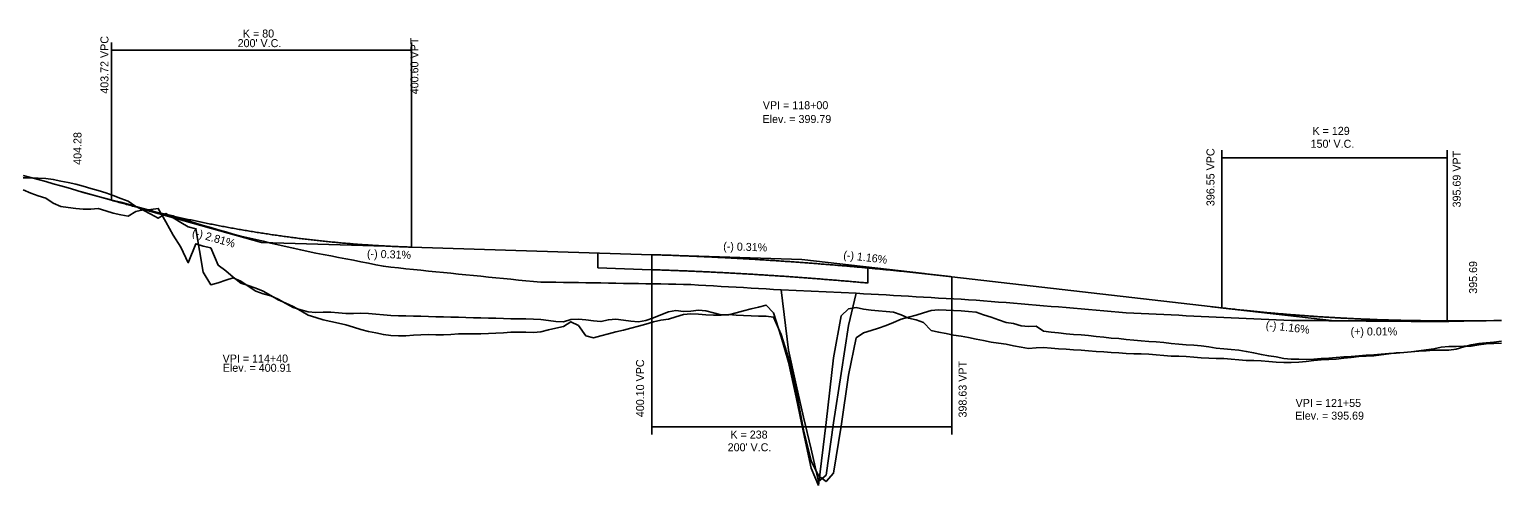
# Model space of a CAD drawing. Extents: x 2084170 to 2089570, y 1072039 to 1077242.
# Drawn here: x 2086175 to 2087155, y 1075386 to 1075690 of the extents above; entities that cross this region are included whole.
import ezdxf

# ---------------------------------------------------------------- set-up
doc = ezdxf.new("R2010")
doc.units = 0
for name, color, linetype in [('RD_DDB_GradeTX', 7, 'Continuous'), ('RD_DDB_Profile_EX', 7, 'Continuous'), ('RD_DDB_Profile_Lbl', 7, 'Continuous'), ('RD_DDB_Profile_PR', 7, 'Continuous'), ('RD_DDB_StripGrade', 7, 'Continuous'), ('RD_DDB_VCLbl', 7, 'Continuous'), ('RD_PD_Bridge', 7, 'Continuous'), ('RD_Sketch1', 7, 'Continuous'), ('RD_Sketch3', 7, 'Continuous'), ('RD_Sketch4', 7, 'Continuous')]:
    doc.layers.add(name, color=color, linetype=linetype)

msp = doc.modelspace()

# ---------------------------------------------------------------- linework, layer by layer
at = {"layer": 'RD_DDB_GradeTX'}
for p, q in [((2086250.56, 1075570.58), (2086329.89, 1075548.31)), ((2086412.25, 1075545.73), (2086329.89, 1075548.31)), ((2086607.53, 1075539.61), (2086689.89, 1075537.03)), ((2086771.75, 1075527.58), (2086689.89, 1075537.03)), ((2086963.04, 1075505.48), (2087044.89, 1075496.03)), ((2087127.29, 1075496.09), (2087044.89, 1075496.03))]:
    msp.add_line(p, q, dxfattribs=at)
at = {"layer": 'RD_DDB_Profile_EX'}
for points in [[(2086171.05, 1075592.84), (2086176.05, 1075591.58), (2086181.05, 1075590.21), (2086186.05, 1075588.83), (2086191.05, 1075587.45), (2086196.05, 1075586.03), (2086201.05, 1075584.6)], [(2086201.05, 1075584.6), (2086206.05, 1075583.14), (2086211.05, 1075581.66), (2086216.05, 1075580.21), (2086221.05, 1075578.94), (2086226.05, 1075577.65), (2086231.05, 1075576.35), (2086236.05, 1075575.03), (2086241.05, 1075573.69), (2086246.05, 1075572.33), (2086251.05, 1075570.96), (2086256.05, 1075569.57), (2086261.05, 1075568.13), (2086266.05, 1075566.73), (2086271.05, 1075565.37), (2086276.05, 1075563.99), (2086281.05, 1075562.6), (2086286.05, 1075561.16), (2086291.05, 1075559.67), (2086296.05, 1075558.24), (2086301.05, 1075556.8), (2086306.05, 1075555.35), (2086311.05, 1075553.85), (2086316.05, 1075552.46), (2086321.05, 1075551.32), (2086326.05, 1075550.2), (2086331.05, 1075549.06), (2086336.05, 1075547.93), (2086341.05, 1075546.79), (2086346.05, 1075545.65), (2086351.05, 1075544.52), (2086356.05, 1075543.38), (2086361.05, 1075542.25), (2086366.05, 1075541.19), (2086371.05, 1075540.24), (2086376.05, 1075539.29), (2086381.05, 1075538.34), (2086386.05, 1075537.38), (2086391.05, 1075536.43), (2086396.05, 1075535.44), (2086401.05, 1075534.46), (2086406.05, 1075533.48), (2086411.05, 1075532.5), (2086416.05, 1075531.8), (2086421.05, 1075531.29), (2086426.05, 1075530.79), (2086431.05, 1075530.28), (2086436.05, 1075529.77), (2086441.05, 1075529.28), (2086446.05, 1075528.77), (2086451.05, 1075528.27), (2086456.05, 1075527.76), (2086461.05, 1075527.25), (2086466.05, 1075526.77), (2086471.05, 1075526.26), (2086476.05, 1075525.75), (2086481.05, 1075525.25), (2086486.05, 1075524.74), (2086491.05, 1075524.26), (2086496.05, 1075523.75), (2086501.05, 1075523.25), (2086506.05, 1075522.75), (2086511.05, 1075522.24), (2086516.05, 1075521.94), (2086521.05, 1075521.85), (2086526.05, 1075521.77), (2086531.05, 1075521.68), (2086536.05, 1075521.6), (2086541.05, 1075521.54), (2086546.05, 1075521.46), (2086551.05, 1075521.37), (2086556.05, 1075521.29), (2086561.05, 1075521.2), (2086566.05, 1075521.14), (2086571.05, 1075521.06), (2086576.05, 1075520.97), (2086581.05, 1075520.89), (2086586.05, 1075520.8), (2086591.05, 1075520.74), (2086596.05, 1075520.65), (2086601.05, 1075520.56), (2086606.05, 1075520.48), (2086611.05, 1075520.39), (2086616.05, 1075520.2), (2086621.05, 1075519.91), (2086626.05, 1075519.61), (2086631.05, 1075519.32), (2086636.05, 1075519.02), (2086641.05, 1075518.79), (2086646.05, 1075518.5), (2086651.05, 1075518.2), (2086656.05, 1075517.91), (2086661.05, 1075517.61), (2086666.05, 1075517.35), (2086671.05, 1075517.06), (2086676.05, 1075516.76), (2086681.05, 1075476.62), (2086686.05, 1075453.49), (2086691.05, 1075431.99), (2086696.05, 1075410.5), (2086701.05, 1075389.01)], [(2086701.05, 1075389.01), (2086706.05, 1075393.3), (2086711.05, 1075428.06), (2086716.05, 1075461.05), (2086721.05, 1075493), (2086726.05, 1075514.45), (2086731.05, 1075514.17), (2086736.05, 1075513.89), (2086741.05, 1075513.6), (2086746.05, 1075513.32), (2086751.05, 1075512.99), (2086756.05, 1075512.71), (2086761.05, 1075512.43), (2086766.05, 1075512.15), (2086771.05, 1075511.87), (2086776.05, 1075511.55), (2086781.05, 1075511.27), (2086786.05, 1075510.99), (2086791.05, 1075510.71), (2086796.05, 1075510.43), (2086801.05, 1075510.12), (2086806.05, 1075509.84), (2086811.05, 1075509.45), (2086816.05, 1075509.03), (2086821.05, 1075508.62), (2086826.05, 1075508.21), (2086831.05, 1075507.8), (2086836.05, 1075507.39), (2086841.05, 1075506.98), (2086846.05, 1075506.57), (2086851.05, 1075506.15), (2086856.05, 1075505.74), (2086861.05, 1075505.31), (2086866.05, 1075504.89), (2086871.05, 1075504.46), (2086876.05, 1075504.04), (2086881.05, 1075503.61), (2086886.05, 1075503.19), (2086891.05, 1075502.76), (2086896.05, 1075502.34), (2086901.05, 1075501.91), (2086906.05, 1075501.49), (2086911.05, 1075501.15), (2086916.05, 1075500.92), (2086921.05, 1075500.69), (2086926.05, 1075500.46), (2086931.05, 1075500.23), (2086936.05, 1075499.99), (2086941.05, 1075499.76), (2086946.05, 1075499.53), (2086951.05, 1075499.3), (2086956.05, 1075499.07), (2086961.05, 1075498.83), (2086966.05, 1075498.6), (2086971.05, 1075498.37), (2086976.05, 1075498.14), (2086981.05, 1075497.91), (2086986.05, 1075497.68), (2086991.05, 1075497.45), (2086996.05, 1075497.22), (2087001.05, 1075496.99), (2087006.05, 1075496.75), (2087011.05, 1075496.52), (2087016.05, 1075496.38), (2087021.05, 1075496.34), (2087026.05, 1075496.31), (2087031.05, 1075496.27), (2087036.05, 1075496.22), (2087041.05, 1075496.18), (2087046.05, 1075496.14), (2087051.05, 1075496.1), (2087056.05, 1075496.05), (2087061.05, 1075496.01), (2087066.05, 1075495.97), (2087071.05, 1075495.93), (2087076.05, 1075495.89), (2087081.05, 1075495.84), (2087086.05, 1075495.8), (2087091.05, 1075495.77), (2087096.05, 1075495.72), (2087101.05, 1075495.68), (2087106.05, 1075495.64), (2087111.05, 1075495.6), (2087116.05, 1075495.67), (2087121.05, 1075495.75), (2087126.05, 1075495.83), (2087131.05, 1075495.91), (2087136.05, 1075496), (2087141.05, 1075496.08), (2087146.05, 1075496.16), (2087151.05, 1075496.24), (2087156.05, 1075496.32)]]:
    msp.add_lwpolyline(points, dxfattribs=at)
at = {"layer": 'RD_DDB_Profile_PR'}
for p, q in [((2086209.89, 1075582), (2086229.89, 1075576.39)), ((2086429.89, 1075545.17), (2086589.89, 1075540.16)), ((2086789.89, 1075525.48), (2086969.89, 1075504.69)), ((2087119.89, 1075496.09), (2087139.89, 1075496.1))]:
    msp.add_line(p, q, dxfattribs=at)
for points in [[(2086229.89, 1075576.39), (2086233.89, 1075575.27), (2086237.89, 1075574.18), (2086241.89, 1075573.11), (2086245.89, 1075572.05), (2086249.89, 1075571.02), (2086253.89, 1075570.01), (2086257.89, 1075569.01), (2086261.89, 1075568.04), (2086265.89, 1075567.09), (2086269.89, 1075566.15), (2086273.89, 1075565.24), (2086277.89, 1075564.35), (2086281.89, 1075563.47), (2086285.89, 1075562.62), (2086289.89, 1075561.78), (2086293.89, 1075560.97), (2086297.89, 1075560.18), (2086301.89, 1075559.4), (2086305.89, 1075558.65), (2086309.89, 1075557.91), (2086313.89, 1075557.2), (2086317.89, 1075556.51), (2086321.89, 1075555.83), (2086325.89, 1075555.18), (2086329.89, 1075554.54), (2086333.89, 1075553.93), (2086337.89, 1075553.33), (2086341.89, 1075552.76), (2086345.89, 1075552.21), (2086349.89, 1075551.67), (2086353.89, 1075551.16), (2086357.89, 1075550.66), (2086361.89, 1075550.19), (2086365.89, 1075549.73), (2086369.89, 1075549.3), (2086373.89, 1075548.88), (2086377.89, 1075548.49), (2086381.89, 1075548.11), (2086385.89, 1075547.76), (2086389.89, 1075547.42), (2086393.89, 1075547.11), (2086397.89, 1075546.82), (2086401.89, 1075546.54), (2086405.89, 1075546.29), (2086409.89, 1075546.05), (2086413.89, 1075545.83), (2086417.89, 1075545.64), (2086421.89, 1075545.46), (2086425.89, 1075545.31), (2086429.89, 1075545.17)], [(2086589.89, 1075540.16), (2086593.89, 1075540.04), (2086597.89, 1075539.9), (2086601.89, 1075539.76), (2086605.89, 1075539.61), (2086609.89, 1075539.45), (2086613.89, 1075539.29), (2086617.89, 1075539.12), (2086621.89, 1075538.95), (2086625.89, 1075538.76), (2086629.89, 1075538.57), (2086633.89, 1075538.38), (2086637.89, 1075538.18), (2086641.89, 1075537.97), (2086645.89, 1075537.75), (2086649.89, 1075537.53), (2086653.89, 1075537.3), (2086657.89, 1075537.06), (2086661.89, 1075536.82), (2086665.89, 1075536.57), (2086669.89, 1075536.31), (2086673.89, 1075536.05), (2086677.89, 1075535.78), (2086681.89, 1075535.5), (2086685.89, 1075535.22), (2086689.89, 1075534.93), (2086693.89, 1075534.63), (2086697.89, 1075534.33), (2086701.89, 1075534.02), (2086705.89, 1075533.7), (2086709.89, 1075533.38), (2086713.89, 1075533.05), (2086717.89, 1075532.71), (2086721.89, 1075532.36), (2086725.89, 1075532.01), (2086729.89, 1075531.66), (2086733.89, 1075531.29), (2086737.89, 1075530.92), (2086741.89, 1075530.54), (2086745.89, 1075530.16), (2086749.89, 1075529.77), (2086753.89, 1075529.37), (2086757.89, 1075528.96), (2086761.89, 1075528.55), (2086765.89, 1075528.13), (2086769.89, 1075527.71), (2086773.89, 1075527.28), (2086777.89, 1075526.84), (2086781.89, 1075526.39), (2086785.89, 1075525.94), (2086789.89, 1075525.48)], [(2086969.89, 1075504.69), (2086972.89, 1075504.35), (2086975.89, 1075504.01), (2086978.89, 1075503.68), (2086981.89, 1075503.36), (2086984.89, 1075503.05), (2086987.89, 1075502.74), (2086990.89, 1075502.44), (2086993.89, 1075502.14), (2086996.89, 1075501.86), (2086999.89, 1075501.58), (2087002.89, 1075501.3), (2087005.89, 1075501.04), (2087008.89, 1075500.78), (2087011.89, 1075500.52), (2087014.89, 1075500.28), (2087017.89, 1075500.04), (2087020.89, 1075499.81), (2087023.89, 1075499.59), (2087026.89, 1075499.37), (2087029.89, 1075499.16), (2087032.89, 1075498.95), (2087035.89, 1075498.76), (2087038.89, 1075498.57), (2087041.89, 1075498.38), (2087044.89, 1075498.21), (2087047.89, 1075498.04), (2087050.89, 1075497.88), (2087053.89, 1075497.72), (2087056.89, 1075497.58), (2087059.89, 1075497.44), (2087062.89, 1075497.3), (2087065.89, 1075497.18), (2087068.89, 1075497.06), (2087071.89, 1075496.94), (2087074.89, 1075496.84), (2087077.89, 1075496.74), (2087080.89, 1075496.65), (2087083.89, 1075496.56), (2087086.89, 1075496.48), (2087089.89, 1075496.41), (2087092.89, 1075496.35), (2087095.89, 1075496.29), (2087098.89, 1075496.24), (2087101.89, 1075496.2), (2087104.89, 1075496.16), (2087107.89, 1075496.13), (2087110.89, 1075496.11), (2087113.89, 1075496.1), (2087116.89, 1075496.09), (2087119.89, 1075496.09)]]:
    msp.add_spline(points, degree=3, dxfattribs=at)
at = {"layer": 'RD_DDB_VCLbl'}
for p, q in [((2086229.89, 1075681.39), (2086229.89, 1075576.39)), ((2086429.89, 1075681.39), (2086429.89, 1075545.17)), ((2086229.89, 1075676.39), (2086429.89, 1075676.39)), ((2086969.89, 1075609.69), (2086969.89, 1075504.69)), ((2086969.89, 1075604.69), (2087119.89, 1075604.69)), ((2087119.89, 1075609.69), (2087119.89, 1075496.09)), ((2086589.89, 1075420.48), (2086589.89, 1075540.16)), ((2086789.89, 1075420.48), (2086789.89, 1075525.48)), ((2086589.89, 1075425.48), (2086789.89, 1075425.48))]:
    msp.add_line(p, q, dxfattribs=at)
at = {"layer": 'RD_PD_Bridge'}
for p, q in [((2086553.89, 1075531.29), (2086553.89, 1075541.29)), ((2086553.89, 1075531.29), (2086589.58, 1075530.17)), ((2086733.89, 1075521.25), (2086733.89, 1075531.29))]:
    msp.add_line(p, q, dxfattribs=at)
msp.add_spline([(2086589.57, 1075530.17), (2086593.56, 1075530.04), (2086597.55, 1075529.91), (2086601.53, 1075529.76), (2086605.51, 1075529.62), (2086609.5, 1075529.46), (2086613.48, 1075529.3), (2086617.46, 1075529.13), (2086621.45, 1075528.96), (2086625.43, 1075528.77), (2086629.41, 1075528.59), (2086633.4, 1075528.39), (2086637.38, 1075528.19), (2086641.36, 1075527.98), (2086645.35, 1075527.77), (2086649.33, 1075527.54), (2086653.31, 1075527.31), (2086657.3, 1075527.08), (2086661.28, 1075526.84), (2086665.26, 1075526.59), (2086669.24, 1075526.33), (2086673.23, 1075526.07), (2086677.21, 1075525.8), (2086681.19, 1075525.53), (2086685.18, 1075525.24), (2086689.16, 1075524.95), (2086693.14, 1075524.66), (2086697.13, 1075524.36), (2086701.11, 1075524.05), (2086705.09, 1075523.73), (2086709.08, 1075523.41), (2086713.06, 1075523.08), (2086717.04, 1075522.74), (2086721.03, 1075522.4), (2086725.01, 1075522.05), (2086728.99, 1075521.7), (2086732.98, 1075521.33), (2086733.89, 1075521.25)], degree=3, dxfattribs=at)
at = {"layer": 'RD_Sketch1'}
msp.add_line((2086676.05, 1075516.76), (2086726.05, 1075514.45), dxfattribs=at)
at = {"layer": 'RD_Sketch3'}
for points in [[(2086171.05, 1075583.29), (2086176.05, 1075581.17), (2086181.05, 1075579.34), (2086186.05, 1075577.81), (2086191.05, 1075574.46), (2086196.05, 1075572.3), (2086201.05, 1075571.49)], [(2086201.05, 1075571.49), (2086206.05, 1075570.92), (2086211.05, 1075570.58), (2086216.05, 1075570.54), (2086221.05, 1075570.93), (2086226.05, 1075569.27), (2086231.05, 1075567.88), (2086236.05, 1075566.75), (2086241.05, 1075565.9), (2086246.05, 1075568.89), (2086251.05, 1075570.01), (2086256.05, 1075570.35), (2086261.05, 1075571.01), (2086266.05, 1075562.13), (2086271.05, 1075553.15), (2086276.05, 1075545.24), (2086281.05, 1075534.74), (2086286.05, 1075547.46), (2086291.05, 1075545.91), (2086296.05, 1075544.78), (2086301.05, 1075533.15), (2086306.05, 1075529.48), (2086311.05, 1075525.09), (2086316.05, 1075521.22), (2086321.05, 1075519.64), (2086326.05, 1075517.89), (2086331.05, 1075515.92), (2086336.05, 1075512.97), (2086341.05, 1075510.08), (2086346.05, 1075507.88), (2086351.05, 1075505.68), (2086356.05, 1075502.73), (2086361.05, 1075499.97), (2086366.05, 1075498.38), (2086371.05, 1075496.78), (2086376.05, 1075495.57), (2086381.05, 1075494.6), (2086386.05, 1075493.51), (2086391.05, 1075491.88), (2086396.05, 1075490.26), (2086401.05, 1075488.96), (2086406.05, 1075488), (2086411.05, 1075486.9), (2086416.05, 1075486.24), (2086421.05, 1075486.12), (2086426.05, 1075486.12), (2086431.05, 1075486.48), (2086436.05, 1075486.85), (2086441.05, 1075486.97), (2086446.05, 1075486.86), (2086451.05, 1075486.77), (2086456.05, 1075487.09), (2086461.05, 1075487.41), (2086466.05, 1075487.52), (2086471.05, 1075487.42), (2086476.05, 1075487.32), (2086481.05, 1075487.56), (2086486.05, 1075487.85), (2086491.05, 1075488.14), (2086496.05, 1075488.43), (2086501.05, 1075488.51), (2086506.05, 1075488.43), (2086511.05, 1075488.34), (2086516.05, 1075488.78), (2086521.05, 1075490), (2086526.05, 1075491.21), (2086531.05, 1075492.42), (2086536.05, 1075495.51), (2086541.05, 1075492.97), (2086546.05, 1075486.18), (2086551.05, 1075484.82), (2086556.05, 1075486.16), (2086561.05, 1075487.5), (2086566.05, 1075488.8), (2086571.05, 1075489.9), (2086576.05, 1075491.22), (2086581.05, 1075492.59), (2086586.05, 1075493.96), (2086591.05, 1075495.33), (2086596.05, 1075496.45), (2086601.05, 1075497.1), (2086606.05, 1075498.74), (2086611.05, 1075500.39), (2086616.05, 1075500.75), (2086621.05, 1075500.46), (2086626.05, 1075500.16), (2086631.05, 1075499.86), (2086636.05, 1075499.82), (2086641.05, 1075500.21), (2086646.05, 1075499.97), (2086651.05, 1075499.74), (2086656.05, 1075499.5), (2086661.05, 1075499.27), (2086666.05, 1075499.12), (2086671.05, 1075498.43), (2086676.05, 1075486.91), (2086681.05, 1075471.48), (2086686.05, 1075449.59), (2086691.05, 1075423.46), (2086696.05, 1075402.85), (2086701.05, 1075392.76)], [(2086701.05, 1075392.76), (2086706.05, 1075389.02), (2086711.05, 1075394.71), (2086716.05, 1075425.99), (2086721.05, 1075459.99), (2086726.05, 1075484.69), (2086731.05, 1075488.04), (2086736.05, 1075489.66), (2086741.05, 1075491.28), (2086746.05, 1075492.9), (2086751.05, 1075494.94), (2086756.05, 1075497.14), (2086761.05, 1075498.54), (2086766.05, 1075499.94), (2086771.05, 1075501.35), (2086776.05, 1075502.89), (2086781.05, 1075503.52), (2086786.05, 1075503.26), (2086791.05, 1075503), (2086796.05, 1075502.74), (2086801.05, 1075502.38), (2086806.05, 1075501.91), (2086811.05, 1075500.19), (2086816.05, 1075498.47), (2086821.05, 1075496.75), (2086826.05, 1075495.02), (2086831.05, 1075494.41), (2086836.05, 1075492.74), (2086841.05, 1075492.27), (2086846.05, 1075492.62), (2086851.05, 1075489.15), (2086856.05, 1075488.6), (2086861.05, 1075488.04), (2086866.05, 1075487.48), (2086871.05, 1075486.93), (2086876.05, 1075486.86), (2086881.05, 1075486.28), (2086886.05, 1075485.7), (2086891.05, 1075485.11), (2086896.05, 1075484.53), (2086901.05, 1075484.29), (2086906.05, 1075483.68), (2086911.05, 1075483.13), (2086916.05, 1075482.77), (2086921.05, 1075482.41), (2086926.05, 1075482.05), (2086931.05, 1075481.68), (2086936.05, 1075481.09), (2086941.05, 1075480.59), (2086946.05, 1075480.2), (2086951.05, 1075479.81), (2086956.05, 1075479.42), (2086961.05, 1075478.74), (2086966.05, 1075477.92), (2086971.05, 1075477.37), (2086976.05, 1075476.94), (2086981.05, 1075476.5), (2086986.05, 1075475.69), (2086991.05, 1075474.68), (2086996.05, 1075473.68), (2087001.05, 1075472.67), (2087006.05, 1075472.08), (2087011.05, 1075471.01), (2087016.05, 1075470.64), (2087021.05, 1075470.52), (2087026.05, 1075470.41), (2087031.05, 1075470.54), (2087036.05, 1075470.92), (2087041.05, 1075471.29), (2087046.05, 1075471.67), (2087051.05, 1075472.04), (2087056.05, 1075472.42), (2087061.05, 1075472.79), (2087066.05, 1075473.17), (2087071.05, 1075473.54), (2087076.05, 1075473.91), (2087081.05, 1075474.29), (2087086.05, 1075474.66), (2087091.05, 1075475.04), (2087096.05, 1075475.41), (2087101.05, 1075475.79), (2087106.05, 1075476.16), (2087111.05, 1075476.52), (2087116.05, 1075476.51), (2087121.05, 1075476.5), (2087126.05, 1075477.32), (2087131.05, 1075478.68), (2087136.05, 1075480.04), (2087141.05, 1075480.92), (2087146.05, 1075481.44), (2087151.05, 1075481.97), (2087156.05, 1075482.49)]]:
    msp.add_lwpolyline(points, dxfattribs=at)
at = {"layer": 'RD_Sketch4'}
for points in [[(2086171.05, 1075591.41), (2086176.05, 1075591.41), (2086181.05, 1075591.22), (2086186.05, 1075590.84), (2086191.05, 1075590.26), (2086196.05, 1075589.22), (2086201.05, 1075588.25)], [(2086201.05, 1075588.25), (2086206.05, 1075587.11), (2086211.05, 1075585.78), (2086216.05, 1075584.28), (2086221.05, 1075582.84), (2086226.05, 1075581.27), (2086231.05, 1075579.52), (2086236.05, 1075577.58), (2086241.05, 1075575.84), (2086246.05, 1075572.28), (2086251.05, 1075569.74), (2086256.05, 1075567.16), (2086261.05, 1075564.43), (2086266.05, 1075567.58), (2086271.05, 1075564.62), (2086276.05, 1075561.61), (2086281.05, 1075558.62), (2086286.05, 1075557.48), (2086291.05, 1075528.61), (2086296.05, 1075520.09), (2086301.05, 1075521.49), (2086306.05, 1075523.07), (2086311.05, 1075524.83), (2086316.05, 1075522.48), (2086321.05, 1075519.12), (2086326.05, 1075515.94), (2086331.05, 1075513.99), (2086336.05, 1075512.75), (2086341.05, 1075510.51), (2086346.05, 1075507.72), (2086351.05, 1075504.93), (2086356.05, 1075503.33), (2086361.05, 1075502.15), (2086366.05, 1075501.68), (2086371.05, 1075501.84), (2086376.05, 1075501.96), (2086381.05, 1075501.52), (2086386.05, 1075501.08), (2086391.05, 1075501), (2086396.05, 1075501.11), (2086401.05, 1075500.99), (2086406.05, 1075500.52), (2086411.05, 1075500.05), (2086416.05, 1075499.74), (2086421.05, 1075499.51), (2086426.05, 1075499.36), (2086431.05, 1075499.28), (2086436.05, 1075499.21), (2086441.05, 1075499.04), (2086446.05, 1075498.81), (2086451.05, 1075498.68), (2086456.05, 1075498.61), (2086461.05, 1075498.54), (2086466.05, 1075498.37), (2086471.05, 1075498.14), (2086476.05, 1075498.03), (2086481.05, 1075497.97), (2086486.05, 1075497.9), (2086491.05, 1075497.74), (2086496.05, 1075497.51), (2086501.05, 1075497.42), (2086506.05, 1075497.36), (2086511.05, 1075497.3), (2086516.05, 1075496.94), (2086521.05, 1075496.27), (2086526.05, 1075495.61), (2086531.05, 1075495.46), (2086536.05, 1075496.89), (2086541.05, 1075497.3), (2086546.05, 1075496.67), (2086551.05, 1075496.03), (2086556.05, 1075495.6), (2086561.05, 1075496.84), (2086566.05, 1075497.17), (2086571.05, 1075496.55), (2086576.05, 1075495.93), (2086581.05, 1075495.32), (2086586.05, 1075496.41), (2086591.05, 1075497.99), (2086596.05, 1075500.06), (2086601.05, 1075502.13), (2086606.05, 1075502.88), (2086611.05, 1075502.33), (2086616.05, 1075502.63), (2086621.05, 1075503.11), (2086626.05, 1075502.83), (2086631.05, 1075501.45), (2086636.05, 1075500.08), (2086641.05, 1075500.05), (2086646.05, 1075501.36), (2086651.05, 1075502.67), (2086656.05, 1075503.98), (2086661.05, 1075505.28), (2086666.05, 1075506.59), (2086671.05, 1075501.32), (2086676.05, 1075485.53), (2086681.05, 1075468.65), (2086686.05, 1075445.25), (2086691.05, 1075421.65), (2086696.05, 1075398.05), (2086701.05, 1075386.35)], [(2086701.05, 1075386.35), (2086706.05, 1075428.32), (2086711.05, 1075471.41), (2086716.05, 1075499.31), (2086721.05, 1075504.11), (2086726.05, 1075504.91), (2086731.05, 1075503.97), (2086736.05, 1075503.16), (2086741.05, 1075502.7), (2086746.05, 1075502.24), (2086751.05, 1075501.78), (2086756.05, 1075500.16), (2086761.05, 1075497.94), (2086766.05, 1075496.65), (2086771.05, 1075494.91), (2086776.05, 1075489.66), (2086781.05, 1075488.65), (2086786.05, 1075487.63), (2086791.05, 1075486.61), (2086796.05, 1075485.84), (2086801.05, 1075484.96), (2086806.05, 1075483.97), (2086811.05, 1075482.97), (2086816.05, 1075481.98), (2086821.05, 1075481.29), (2086826.05, 1075480.46), (2086831.05, 1075479.49), (2086836.05, 1075478.6), (2086841.05, 1075477.68), (2086846.05, 1075478.16), (2086851.05, 1075478.24), (2086856.05, 1075477.85), (2086861.05, 1075477.47), (2086866.05, 1075477.12), (2086871.05, 1075476.83), (2086876.05, 1075476.5), (2086881.05, 1075476.11), (2086886.05, 1075475.72), (2086891.05, 1075475.37), (2086896.05, 1075475.09), (2086901.05, 1075474.75), (2086906.05, 1075474.36), (2086911.05, 1075474.15), (2086916.05, 1075474.08), (2086921.05, 1075473.85), (2086926.05, 1075473.4), (2086931.05, 1075472.95), (2086936.05, 1075472.64), (2086941.05, 1075472.56), (2086946.05, 1075472.36), (2086951.05, 1075471.91), (2086956.05, 1075471.47), (2086961.05, 1075471.16), (2086966.05, 1075471.09), (2086971.05, 1075470.91), (2086976.05, 1075470.47), (2086981.05, 1075470.03), (2086986.05, 1075469.72), (2086991.05, 1075469.65), (2086996.05, 1075469.49), (2087001.05, 1075469.06), (2087006.05, 1075468.62), (2087011.05, 1075468.27), (2087016.05, 1075468.36), (2087021.05, 1075468.56), (2087026.05, 1075469), (2087031.05, 1075469.58), (2087036.05, 1075470.16), (2087041.05, 1075470.42), (2087046.05, 1075470.62), (2087051.05, 1075471.16), (2087056.05, 1075471.77), (2087061.05, 1075472.38), (2087066.05, 1075472.65), (2087071.05, 1075472.86), (2087076.05, 1075473.5), (2087081.05, 1075474.15), (2087086.05, 1075474.8), (2087091.05, 1075475.07), (2087096.05, 1075475.41), (2087101.05, 1075476.11), (2087106.05, 1075476.81), (2087111.05, 1075477.51), (2087116.05, 1075478.5), (2087121.05, 1075478.96), (2087126.05, 1075479.08), (2087131.05, 1075479.19), (2087136.05, 1075479.31), (2087141.05, 1075480.16), (2087146.05, 1075480.83), (2087151.05, 1075480.99), (2087156.05, 1075481.15)]]:
    msp.add_lwpolyline(points, dxfattribs=at)

# ---------------------------------------------------------------- texts
at = {"layer": 'RD_DDB_GradeTX'}
for s, rotation, p in [('(-) 2.81%', 344.31387, (2086283.21, 1075552.71)), ('(-) 0.31%', 358.20647, (2086400.08, 1075538.24)), ('(-) 0.31%', 358.20647, (2086637.44, 1075543.19)), ('(-) 1.16%', 353.41138, (2086717.35, 1075537.49)), ('(-) 1.16%', 353.41138, (2086998.85, 1075490.83)), ('(+) 0.01%', 0.04361, (2087055.57, 1075486.33))]:
    msp.add_text(s, height=5.333, rotation=rotation, dxfattribs=at).set_placement(p)
at = {"layer": 'RD_DDB_Profile_Lbl'}
for s, p in [('VPI = 118+00', (2086663.93, 1075637.03)), ('Elev. = 399.79', (2086663.72, 1075627.84)), ('VPI = 114+40', (2086303.93, 1075468.31)), ('Elev. = 400.91', (2086304.04, 1075462.15)), ('VPI = 121+55', (2087018.96, 1075438.73)), ('Elev. = 395.69', (2087018.72, 1075430.27))]:
    msp.add_text(s, height=5.3331, dxfattribs=at).set_placement(p)
for s, p in [('404.28', (2086209.89, 1075600)), ('395.69', (2087139.89, 1075514.1))]:
    msp.add_text(s, height=5.333, rotation=90, dxfattribs=at).set_placement(p)
at = {"layer": 'RD_DDB_StripGrade'}
for s, p in [('403.72 VPC', (2086227.86, 1075647.37)), ('400.60 VPT', (2086434.4, 1075647.03)), ('396.55 VPC', (2086964.89, 1075572.5)), ('395.69 VPT', (2087128.98, 1075571.63)), ('400.10 VPC', (2086584.8, 1075431.93)), ('398.63 VPT', (2086799.7, 1075431.7))]:
    msp.add_text(s, height=5.333, rotation=90, dxfattribs=at).set_placement(p)
at = {"layer": 'RD_DDB_VCLbl'}
for s, p in [('K = 80', (2086317.43, 1075684.79)), ("200' V.C.", (2086313.95, 1075678.39)), ('K = 129', (2087030.23, 1075619.97)), ("150' V.C.", (2087028.95, 1075611.37)), ('K = 238', (2086642.33, 1075417.66)), ("200' V.C.", (2086640.51, 1075409.2))]:
    msp.add_text(s, height=5.333, dxfattribs=at).set_placement(p)

doc.saveas('drawing.dxf')
